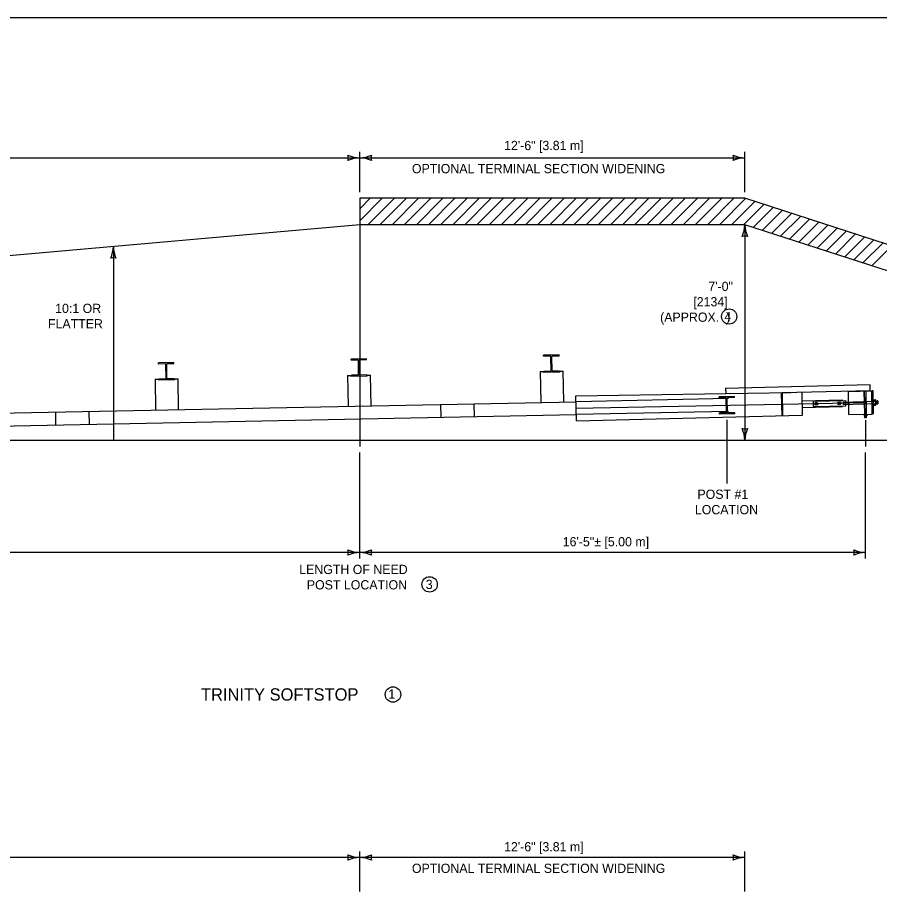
# Model space of a CAD drawing. Extents: x 49991.4 to 50021, y 49987.6 to 50011.4.
# Drawn here: x 50006.31 to 50011.91, y 49993.3 to 49999 of the extents above; entities that cross this region are included whole.
import ezdxf

# ---------------------------------------------------------------- set-up
doc = ezdxf.new("R2010")
doc.units = 0
for name, color, linetype in [('Level 1', 7, 'Continuous'), ('Level 2', 7, 'Continuous'), ('Level 3', 7, 'Continuous'), ('Level 5', 7, 'Continuous')]:
    doc.layers.add(name, color=color, linetype=linetype)

msp = doc.modelspace()

# ---------------------------------------------------------------- linework, layer by layer
at = {"layer": 'Level 1'}
for p, q in [((50011.0311, 49997.8254), (50008.5311, 49997.8254)), ((50008.5311, 49997.8254), (50008.5311, 49997.6537)), ((50008.6772, 49997.8254), (50008.5311, 49997.6793)), ((50008.5985, 49997.8254), (50008.5311, 49997.758)), ((50008.7559, 49997.8254), (50008.5841, 49997.6537)), ((50008.8346, 49997.8254), (50008.6628, 49997.6537)), ((50008.9133, 49997.8254), (50008.7415, 49997.6537)), ((50008.992, 49997.8254), (50008.8202, 49997.6537)), ((50009.0707, 49997.8254), (50008.8989, 49997.6537)), ((50009.1494, 49997.8254), (50008.9776, 49997.6537)), ((50009.2281, 49997.8254), (50009.0563, 49997.6537)), ((50009.3068, 49997.8254), (50009.135, 49997.6537)), ((50009.3855, 49997.8254), (50009.2137, 49997.6537)), ((50009.4642, 49997.8254), (50009.2924, 49997.6537)), ((50009.5429, 49997.8254), (50009.3711, 49997.6537)), ((50009.6216, 49997.8254), (50009.4498, 49997.6537)), ((50009.7003, 49997.8254), (50009.5286, 49997.6537)), ((50009.779, 49997.8254), (50009.6073, 49997.6537)), ((50009.8577, 49997.8254), (50009.686, 49997.6537)), ((50009.9364, 49997.8254), (50009.7647, 49997.6537)), ((50010.0151, 49997.8254), (50009.8434, 49997.6537)), ((50010.0938, 49997.8254), (50009.9221, 49997.6537)), ((50010.1725, 49997.8254), (50010.0008, 49997.6537)), ((50010.2512, 49997.8254), (50010.0795, 49997.6537)), ((50010.3299, 49997.8254), (50010.1582, 49997.6537)), ((50010.4086, 49997.8254), (50010.2369, 49997.6537)), ((50010.4873, 49997.8254), (50010.3156, 49997.6537)), ((50010.5661, 49997.8254), (50010.3943, 49997.6537)), ((50010.6448, 49997.8254), (50010.473, 49997.6537)), ((50010.7235, 49997.8254), (50010.5517, 49997.6537)), ((50010.8022, 49997.8254), (50010.6304, 49997.6537)), ((50010.8809, 49997.8254), (50010.7091, 49997.6537)), ((50010.9596, 49997.8254), (50010.7878, 49997.6537)), ((50015.8765, 49996.2537), (50011.0311, 49997.8254)), ((50011.0365, 49997.8236), (50010.8665, 49997.6537)), ((50011.0959, 49997.8044), (50010.9451, 49997.6537)), ((50011.1552, 49997.7851), (50011.0236, 49997.6537)), ((50011.2144, 49997.7659), (50011.0848, 49997.6362)), ((50011.2738, 49997.7467), (50011.1441, 49997.617)), ((50011.3331, 49997.7274), (50011.2035, 49997.5977)), ((50011.3924, 49997.7082), (50011.2628, 49997.5785)), ((50011.4518, 49997.6889), (50011.322, 49997.5593)), ((50011.5112, 49997.6697), (50011.3814, 49997.54)), ((50008.5311, 49997.6537), (50001.6559, 49997.0447)), ((50011.0311, 49997.6537), (50008.5311, 49997.6537)), ((50015.3468, 49996.2537), (50011.0311, 49997.6537)), ((50011.5704, 49997.6505), (50011.4407, 49997.5208)), ((50011.6297, 49997.6312), (50011.5, 49997.5015)), ((50011.6891, 49997.612), (50011.5594, 49997.4823)), ((50011.7484, 49997.5927), (50011.6187, 49997.463)), ((50011.8077, 49997.5735), (50011.678, 49997.4438)), ((50011.8671, 49997.5542), (50011.7373, 49997.4245)), ((50011.9264, 49997.535), (50011.7967, 49997.4053)), ((50011.9857, 49997.5158), (50011.856, 49997.386)), ((50009.8249, 49996.8081), (50009.7252, 49996.8061)), ((50009.7253, 49996.7993), (50009.7252, 49996.8061)), ((50009.7723, 49996.8002), (50009.7253, 49996.7993)), ((50009.7742, 49996.7019), (50009.7723, 49996.8002)), ((50009.825, 49996.8013), (50009.7781, 49996.8003)), ((50009.78, 49996.702), (50009.7781, 49996.8003)), ((50009.825, 49996.8013), (50009.8249, 49996.8081)), ((50007.3249, 49996.7581), (50007.2252, 49996.7561)), ((50007.2253, 49996.7493), (50007.2252, 49996.7561)), ((50007.2723, 49996.7502), (50007.2253, 49996.7493)), ((50007.2742, 49996.6519), (50007.2723, 49996.7502)), ((50007.325, 49996.7513), (50007.2781, 49996.7503)), ((50007.28, 49996.652), (50007.2781, 49996.7503)), ((50007.325, 49996.7513), (50007.3249, 49996.7581)), ((50008.5749, 49996.7831), (50008.4752, 49996.7811)), ((50008.4753, 49996.7743), (50008.4752, 49996.7811)), ((50008.5223, 49996.7752), (50008.4753, 49996.7743)), ((50008.5242, 49996.6769), (50008.5223, 49996.7752)), ((50008.575, 49996.7763), (50008.5281, 49996.7753)), ((50008.53, 49996.677), (50008.5281, 49996.7753)), ((50008.575, 49996.7763), (50008.5749, 49996.7831)), ((50009.7023, 49996.6999), (50009.7242, 49996.7003)), ((50009.7023, 49996.6999), (50009.7063, 49996.4999)), ((50009.7242, 49996.7003), (50009.7243, 49996.6942)), ((50009.8301, 49996.6963), (50009.7243, 49996.6942)), ((50009.7742, 49996.7019), (50009.7273, 49996.701)), ((50009.7274, 49996.6942), (50009.7273, 49996.701)), ((50009.827, 49996.703), (50009.78, 49996.702)), ((50009.8271, 49996.6962), (50009.827, 49996.703)), ((50009.83, 49996.7025), (50009.8518, 49996.7029)), ((50009.8301, 49996.6963), (50009.83, 49996.7025)), ((50009.8558, 49996.5029), (50009.8518, 49996.7029)), ((50007.2023, 49996.6499), (50007.2242, 49996.6503)), ((50007.2023, 49996.6499), (50007.2063, 49996.4499)), ((50007.2242, 49996.6503), (50007.2243, 49996.6442)), ((50007.3301, 49996.6463), (50007.2243, 49996.6442)), ((50007.2742, 49996.6519), (50007.2273, 49996.651)), ((50007.2274, 49996.6442), (50007.2273, 49996.651)), ((50007.327, 49996.653), (50007.28, 49996.652)), ((50007.3271, 49996.6462), (50007.327, 49996.653)), ((50007.33, 49996.6525), (50007.3518, 49996.6529)), ((50007.3301, 49996.6463), (50007.33, 49996.6525)), ((50007.3558, 49996.4529), (50007.3518, 49996.6529)), ((50008.4523, 49996.6749), (50008.4742, 49996.6753)), ((50008.4523, 49996.6749), (50008.4563, 49996.4749)), ((50008.4742, 49996.6753), (50008.4743, 49996.6692)), ((50008.5801, 49996.6713), (50008.4743, 49996.6692)), ((50008.5242, 49996.6769), (50008.4773, 49996.676)), ((50008.4774, 49996.6692), (50008.4773, 49996.676)), ((50008.577, 49996.678), (50008.53, 49996.677)), ((50008.5771, 49996.6712), (50008.577, 49996.678)), ((50008.58, 49996.6775), (50008.6018, 49996.6779)), ((50008.5801, 49996.6713), (50008.58, 49996.6775)), ((50008.6058, 49996.4779), (50008.6018, 49996.6779)), ((50011.8446, 49996.6141), (50010.9067, 49996.5906)), ((50010.9067, 49996.5921), (50010.9076, 49996.5562)), ((50011.8456, 49996.5741), (50011.2728, 49996.5622)), ((50011.7049, 49996.5705), (50011.8549, 49996.5743)), ((50011.8047, 49996.573), (50011.8071, 49996.4233)), ((50011.8067, 49996.5731), (50011.8091, 49996.4234)), ((50011.8165, 49996.5735), (50011.8189, 49996.4236)), ((50011.8209, 49996.4237), (50011.8185, 49996.5734)), ((50011.8456, 49996.5741), (50011.8446, 49996.6141)), ((50011.8641, 49996.5745), (50011.8549, 49996.5743)), ((50011.8573, 49996.4246), (50011.8549, 49996.5743)), ((50011.8665, 49996.4248), (50011.8641, 49996.5745)), ((50009.9344, 49996.542), (50011.3292, 49996.5642)), ((50009.9377, 49996.3809), (50009.9344, 49996.542)), ((50010.9244, 49996.5244), (50009.9352, 49996.5045)), ((50010.9636, 49996.5383), (50010.8639, 49996.5363)), ((50010.8641, 49996.5295), (50010.8639, 49996.5363)), ((50010.911, 49996.5304), (50010.8641, 49996.5295)), ((50010.913, 49996.4321), (50010.911, 49996.5304)), ((50010.9638, 49996.5315), (50010.9168, 49996.5306)), ((50010.9188, 49996.4322), (50010.9168, 49996.5306)), ((50010.9638, 49996.5315), (50010.9636, 49996.5383)), ((50011.2678, 49996.5621), (50011.2708, 49996.4113)), ((50011.2728, 49996.5622), (50011.2758, 49996.4114)), ((50011.4012, 49996.5642), (50011.4036, 49996.4145)), ((50011.4023, 49996.511), (50011.6641, 49996.5163)), ((50011.6642, 49996.5124), (50011.6641, 49996.5163)), ((50011.7073, 49996.4211), (50011.7049, 49996.5708)), ((50011.8672, 49996.5197), (50011.865, 49996.5196)), ((50011.8679, 49996.4798), (50011.8672, 49996.5197)), ((50011.8673, 49996.5172), (50011.8777, 49996.5174)), ((50001.6561, 49996.3389), (50009.9352, 49996.5045)), ((50009.0557, 49996.4869), (50009.0574, 49996.4032)), ((50009.2723, 49996.4913), (50009.274, 49996.4075)), ((50009.936, 49996.4615), (50011.8227, 49996.4992)), ((50011.4025, 49996.4676), (50011.665, 49996.4729)), ((50011.4741, 49996.5086), (50011.686, 49996.5128)), ((50011.4741, 49996.5086), (50011.4748, 49996.473)), ((50011.4748, 49996.473), (50011.6868, 49996.4772)), ((50011.6649, 49996.4768), (50011.665, 49996.4729)), ((50011.6692, 49996.5022), (50011.8653, 49996.5071)), ((50011.6692, 49996.5022), (50011.6695, 49996.4872)), ((50011.6695, 49996.4872), (50011.8654, 49996.4922)), ((50011.6863, 49996.4976), (50011.686, 49996.5128)), ((50011.6868, 49996.4772), (50011.6864, 49996.4927)), ((50011.8652, 49996.5096), (50011.8559, 49996.5094)), ((50011.8655, 49996.4897), (50011.8563, 49996.4895)), ((50011.8674, 49996.5103), (50011.8652, 49996.5102)), ((50011.8677, 49996.4891), (50011.8655, 49996.489)), ((50011.8679, 49996.4798), (50011.8657, 49996.4797)), ((50011.8674, 49996.5084), (50011.8778, 49996.5087)), ((50011.8677, 49996.491), (50011.8781, 49996.4912)), ((50011.8678, 49996.4822), (50011.8782, 49996.4825)), ((50011.8811, 49996.5128), (50011.8815, 49996.4873)), ((50011.8812, 49996.5096), (50011.8814, 49996.5101)), ((50011.8824, 49996.4913), (50011.8814, 49996.5101)), ((50011.8814, 49996.5101), (50011.8822, 49996.5088)), ((50011.8817, 49996.4901), (50011.8814, 49996.4954)), ((50011.8815, 49996.4904), (50011.8817, 49996.4901)), ((50011.8824, 49996.4913), (50011.8817, 49996.4901)), ((50011.8829, 49996.5101), (50011.8822, 49996.5088)), ((50011.8833, 49996.4901), (50011.8822, 49996.5088)), ((50011.8824, 49996.4913), (50011.8833, 49996.4901)), ((50011.884, 49996.4914), (50011.8829, 49996.5101)), ((50011.8829, 49996.5101), (50011.8837, 49996.5089)), ((50011.884, 49996.4914), (50011.8833, 49996.4901)), ((50011.8845, 49996.5101), (50011.8837, 49996.5089)), ((50011.8848, 49996.4902), (50011.8837, 49996.5089)), ((50011.884, 49996.4914), (50011.8848, 49996.4902)), ((50011.8856, 49996.4914), (50011.8845, 49996.5101)), ((50011.8845, 49996.5101), (50011.8853, 49996.5089)), ((50011.8856, 49996.4914), (50011.8848, 49996.4902)), ((50011.886, 49996.5102), (50011.8853, 49996.5089)), ((50011.8863, 49996.4902), (50011.8853, 49996.5089)), ((50011.8856, 49996.4914), (50011.8863, 49996.4902)), ((50011.8871, 49996.4914), (50011.886, 49996.5102)), ((50011.886, 49996.5102), (50011.8868, 49996.5089)), ((50011.8871, 49996.4914), (50011.8863, 49996.4902)), ((50011.8876, 49996.5102), (50011.8868, 49996.5089)), ((50011.8879, 49996.4902), (50011.8868, 49996.5089)), ((50011.8871, 49996.4914), (50011.8879, 49996.4902)), ((50011.8886, 49996.4915), (50011.8876, 49996.5102)), ((50011.8876, 49996.5102), (50011.8884, 49996.509)), ((50011.8886, 49996.4915), (50011.8879, 49996.4902)), ((50011.8891, 49996.5103), (50011.8884, 49996.509)), ((50011.8895, 49996.4903), (50011.8884, 49996.509)), ((50011.8886, 49996.4915), (50011.8895, 49996.4903)), ((50011.8902, 49996.4915), (50011.8891, 49996.5103)), ((50011.8891, 49996.5103), (50011.8899, 49996.509)), ((50011.8902, 49996.4915), (50011.8895, 49996.4903)), ((50011.8907, 49996.5103), (50011.8899, 49996.509)), ((50011.891, 49996.4903), (50011.8899, 49996.509)), ((50011.8902, 49996.4915), (50011.891, 49996.4903)), ((50011.8918, 49996.4915), (50011.8907, 49996.5103)), ((50011.8907, 49996.5103), (50011.8915, 49996.509)), ((50011.8918, 49996.4915), (50011.891, 49996.4903)), ((50011.8922, 49996.5103), (50011.8915, 49996.509)), ((50011.8925, 49996.4904), (50011.8915, 49996.509)), ((50011.8918, 49996.4915), (50011.8925, 49996.4904)), ((50011.8933, 49996.4916), (50011.8922, 49996.5103)), ((50011.8922, 49996.5103), (50011.893, 49996.5091)), ((50011.8933, 49996.4916), (50011.8925, 49996.4904)), ((50011.8938, 49996.5104), (50011.893, 49996.5091)), ((50011.8941, 49996.4904), (50011.893, 49996.5091)), ((50011.8933, 49996.4916), (50011.8941, 49996.4904)), ((50011.8948, 49996.4916), (50011.8938, 49996.5104)), ((50011.8938, 49996.5104), (50011.8946, 49996.5091)), ((50011.8948, 49996.4916), (50011.8941, 49996.4904)), ((50011.8946, 49996.5091), (50011.8948, 49996.4916)), ((50001.6561, 49996.2551), (50009.9369, 49996.4208)), ((50006.5557, 49996.4369), (50006.5574, 49996.3532)), ((50006.7723, 49996.4413), (50006.774, 49996.3575)), ((50010.926, 49996.4407), (50009.9369, 49996.4208)), ((50009.9377, 49996.3809), (50011.4035, 49996.4162)), ((50010.913, 49996.4321), (50010.866, 49996.4312)), ((50010.8662, 49996.4245), (50010.866, 49996.4312)), ((50010.9659, 49996.4264), (50010.8662, 49996.4245)), ((50010.9657, 49996.4332), (50010.9188, 49996.4322)), ((50010.9659, 49996.4264), (50010.9657, 49996.4332)), ((50011.7073, 49996.4208), (50011.8573, 49996.4246)), ((50011.8042, 49996.4232), (50011.8238, 49996.4237)), ((50011.8042, 49996.4215), (50011.8042, 49996.4232)), ((50011.8042, 49996.4215), (50011.8239, 49996.422)), ((50011.8054, 49996.4216), (50011.8056, 49996.4133)), ((50011.8207, 49996.4111), (50011.8077, 49996.4107)), ((50011.8088, 49996.4217), (50011.8088, 49996.4234)), ((50011.8093, 49996.4106), (50011.8109, 49996.4108)), ((50011.8095, 49996.4108), (50011.8093, 49996.4106)), ((50011.8099, 49996.41), (50011.8093, 49996.4106)), ((50011.8093, 49996.4094), (50011.8185, 49996.4102)), ((50011.8099, 49996.41), (50011.8093, 49996.4094)), ((50011.8099, 49996.4088), (50011.8093, 49996.4094)), ((50011.8093, 49996.4082), (50011.8185, 49996.409)), ((50011.8099, 49996.4088), (50011.8093, 49996.4082)), ((50011.8099, 49996.4076), (50011.8093, 49996.4082)), ((50011.8094, 49996.4069), (50011.8186, 49996.4078)), ((50011.8099, 49996.4076), (50011.8094, 49996.4069)), ((50011.81, 49996.4064), (50011.8094, 49996.4069)), ((50011.8094, 49996.4057), (50011.8186, 49996.4066)), ((50011.81, 49996.4064), (50011.8094, 49996.4057)), ((50011.81, 49996.4051), (50011.8094, 49996.4057)), ((50011.8094, 49996.4045), (50011.8186, 49996.4053)), ((50011.81, 49996.4051), (50011.8094, 49996.4045)), ((50011.81, 49996.4039), (50011.8094, 49996.4045)), ((50011.8094, 49996.4033), (50011.8186, 49996.4041)), ((50011.81, 49996.4039), (50011.8094, 49996.4033)), ((50011.81, 49996.4027), (50011.8094, 49996.4033)), ((50011.8094, 49996.402), (50011.8186, 49996.4029)), ((50011.81, 49996.4027), (50011.8094, 49996.402)), ((50011.81, 49996.4015), (50011.8094, 49996.402)), ((50011.8095, 49996.4008), (50011.8187, 49996.4017)), ((50011.8183, 49996.4236), (50011.8097, 49996.4234)), ((50011.8098, 49996.4217), (50011.8099, 49996.4134)), ((50011.8099, 49996.41), (50011.8191, 49996.4109)), ((50011.8099, 49996.4088), (50011.8192, 49996.4096)), ((50011.8099, 49996.4076), (50011.8192, 49996.4084)), ((50011.81, 49996.4064), (50011.8192, 49996.4072)), ((50011.81, 49996.4051), (50011.8192, 49996.406)), ((50011.81, 49996.4039), (50011.8192, 49996.4047)), ((50011.81, 49996.4027), (50011.8193, 49996.4035)), ((50011.81, 49996.4015), (50011.8193, 49996.4023)), ((50011.8183, 49996.4219), (50011.8185, 49996.4137)), ((50011.8191, 49996.4109), (50011.8185, 49996.4102)), ((50011.8192, 49996.4096), (50011.8185, 49996.4102)), ((50011.8192, 49996.4096), (50011.8185, 49996.409)), ((50011.8192, 49996.4084), (50011.8185, 49996.409)), ((50011.8192, 49996.4084), (50011.8186, 49996.4078)), ((50011.8192, 49996.4072), (50011.8186, 49996.4078)), ((50011.8192, 49996.4072), (50011.8186, 49996.4066)), ((50011.8192, 49996.406), (50011.8186, 49996.4066)), ((50011.8192, 49996.406), (50011.8186, 49996.4053)), ((50011.8192, 49996.4047), (50011.8186, 49996.4053)), ((50011.8192, 49996.4047), (50011.8186, 49996.4041)), ((50011.8193, 49996.4035), (50011.8186, 49996.4041)), ((50011.8193, 49996.4035), (50011.8186, 49996.4029)), ((50011.8193, 49996.4023), (50011.8186, 49996.4029)), ((50011.8193, 49996.4023), (50011.8187, 49996.4017)), ((50011.8193, 49996.4011), (50011.8187, 49996.4017)), ((50011.8191, 49996.4109), (50011.819, 49996.411)), ((50011.8193, 49996.4219), (50011.8192, 49996.4236)), ((50011.8226, 49996.422), (50011.8228, 49996.4138)), ((50011.8239, 49996.422), (50011.8238, 49996.4237)), ((50011.8665, 49996.4248), (50011.8573, 49996.4246)), ((50011.81, 49996.4015), (50011.8095, 49996.4008)), ((50011.8101, 49996.4002), (50011.8095, 49996.4008)), ((50011.8101, 49996.4002), (50011.8193, 49996.4011)), ((50011.8187, 49996.4004), (50011.8101, 49996.4002)), ((50011.8193, 49996.4011), (50011.8187, 49996.4004)), ((50000.2381, 49996.2551), (50015.8765, 49996.2537))]:
    msp.add_line(p, q, dxfattribs=at)
msp.add_lwpolyline([(49999.3835, 49998.9992), (50016.7501, 49998.9992), (50016.7501, 49987.7988), (49999.3835, 49987.7988)], close=True, dxfattribs=at)
for centre, radius in [((50011.4945, 49996.4912), 0.00975), ((50011.4945, 49996.4912), 0.00775), ((50011.6439, 49996.4942), 0.00975), ((50011.6439, 49996.4942), 0.00775)]:
    msp.add_circle(centre, radius, dxfattribs=at)
for centre, major_axis, start_param, end_param in [((50011.8777, 49996.5131), (0, 0.00431), 4.714734, 6.30331), ((50011.8777, 49996.513), (0, -0.00431), 0.020125, 1.600918), ((50011.8779, 49996.5044), (0, 0.00431), 4.793382, 6.30331), ((50011.878, 49996.4956), (0, -0.00431), 0.020125, 1.530052), ((50011.8781, 49996.4869), (0, 0.00431), 4.732514, 6.30331), ((50011.8781, 49996.4868), (0, -0.00431), 0.020125, 1.618692), ((50011.8077, 49996.4134), (0, -0.00267), 4.73531, 6.306106), ((50011.8077, 49996.4134), (0, 0.00272), 3.140677, 4.711474), ((50011.812, 49996.4135), (0, -0.00267), 4.733592, 6.253409), ((50011.8164, 49996.4136), (0, 0.00268), 3.197527, 4.725448), ((50011.8206, 49996.4138), (0, -0.0027), 4.748152, 6.318948), ((50011.8207, 49996.4137), (0, 0.00268), 3.153377, 4.724173)]:
    msp.add_ellipse(centre, major_axis=major_axis, ratio=0.790231, start_param=start_param, end_param=end_param, dxfattribs=at)
at = {"layer": 'Level 2'}
for centre, radius in [((50010.9297, 49997.0577), 0.0492), ((50008.985, 49995.3182), 0.05), ((50008.7474, 49994.6034), 0.05)]:
    msp.add_circle(centre, radius, dxfattribs=at)
at = {"layer": 'Level 3'}
for p, q in [((50008.5311, 49998.0882), (50008.5311, 49998.1282)), ((50011.0311, 49998.0882), (50011.0311, 49998.1282)), ((50001.6559, 49998.0882), (50008.5311, 49998.0882)), ((50008.5311, 49997.8654), (50008.5311, 49998.0882)), ((50008.5311, 49998.0882), (50011.0311, 49998.0882)), ((50011.0311, 49997.8654), (50011.0311, 49998.0882)), ((50011.0311, 49997.6537), (50011.0311, 49996.2542)), ((50006.9319, 49997.512), (50006.9319, 49996.2546)), ((50008.531, 49995.4854), (50008.531, 49996.1744)), ((50011.8144, 49995.4854), (50011.8144, 49996.174)), ((50008.531, 49995.5254), (50001.6561, 49995.5254)), ((50011.8144, 49995.5254), (50008.531, 49995.5254)), ((50008.5311, 49993.3247), (50008.5311, 49993.5845)), ((50011.0311, 49993.3247), (50011.0311, 49993.5845)), ((50008.5311, 49993.5445), (50001.6559, 49993.5445)), ((50011.0311, 49993.5445), (50008.5311, 49993.5445))]:
    msp.add_line(p, q, dxfattribs=at)
for centre, radius, start, end in [((50008.5402, 49998.3103), 0.2223, 247.456, 267.6395), ((50008.4028, 49998.0882), 0.0548, 342.1388, 17.8612), ((50008.5425, 49997.8555), 0.233, 92.8273, 112.0772), ((50008.5196, 49998.3209), 0.233, 272.8273, 292.0772), ((50008.5196, 49998.3209), 0.233, 272.8273, 292.0772), ((50008.5219, 49997.8661), 0.2223, 67.456, 87.6395), ((50008.5219, 49997.8661), 0.2223, 67.456, 87.6395), ((50008.6593, 49998.0882), 0.0548, 162.1388, 197.8612), ((50008.6593, 49998.0882), 0.0548, 162.1388, 197.8612), ((50011.0402, 49998.3103), 0.2223, 247.456, 267.6395), ((50010.9028, 49998.0882), 0.0548, 342.1388, 17.8612), ((50011.0402, 49998.3103), 0.2223, 247.456, 267.6395), ((50010.9028, 49998.0882), 0.0548, 342.1388, 17.8612), ((50011.0425, 49997.8555), 0.233, 92.8273, 112.0772), ((50011.0425, 49997.8555), 0.233, 92.8273, 112.0772), ((50010.8089, 49997.6628), 0.2223, 337.456, 357.6395), ((50011.2638, 49997.6651), 0.233, 182.8273, 202.0772), ((50011.0311, 49997.5254), 0.0548, 72.1388, 107.8612), ((50006.7097, 49997.5212), 0.2223, 337.456, 357.6395), ((50007.1646, 49997.5235), 0.233, 182.8273, 202.0772), ((50006.9319, 49997.3838), 0.0548, 72.1388, 107.8612), ((50011.0311, 49996.3824), 0.0548, 252.1388, 287.8612), ((50010.7983, 49996.2427), 0.233, 2.8273, 22.0772), ((50011.2532, 49996.245), 0.2223, 157.456, 177.6395), ((50008.5402, 49995.7476), 0.2223, 247.456, 267.6395), ((50008.4028, 49995.5254), 0.0548, 342.1388, 17.8612), ((50008.5402, 49995.7476), 0.2223, 247.456, 267.6395), ((50008.4028, 49995.5254), 0.0548, 342.1388, 17.8612), ((50008.5425, 49995.2927), 0.233, 92.8273, 112.0772), ((50008.5425, 49995.2927), 0.233, 92.8273, 112.0772), ((50008.5195, 49995.7581), 0.233, 272.8273, 292.0772), ((50008.5219, 49995.3033), 0.2223, 67.456, 87.6395), ((50008.6592, 49995.5254), 0.0548, 162.1388, 197.8612), ((50011.8235, 49995.7476), 0.2223, 247.456, 267.6395), ((50011.6862, 49995.5254), 0.0548, 342.1388, 17.8612), ((50011.8259, 49995.2927), 0.233, 92.8273, 112.0772), ((50008.5402, 49993.7666), 0.2223, 247.456, 267.6395), ((50008.4028, 49993.5445), 0.0548, 342.1388, 17.8612), ((50008.5402, 49993.7666), 0.2223, 247.456, 267.6395), ((50008.4028, 49993.5445), 0.0548, 342.1388, 17.8612), ((50008.5196, 49993.7772), 0.233, 272.8273, 292.0772), ((50008.6593, 49993.5445), 0.0548, 162.1388, 197.8612), ((50011.0402, 49993.7666), 0.2223, 247.456, 267.6395), ((50010.9028, 49993.5445), 0.0548, 342.1388, 17.8612), ((50008.5425, 49993.3118), 0.233, 92.8273, 112.0772), ((50008.5425, 49993.3118), 0.233, 92.8273, 112.0772), ((50008.5219, 49993.3223), 0.2223, 67.456, 87.6395), ((50011.0425, 49993.3118), 0.233, 92.8273, 112.0772)]:
    msp.add_arc(centre, radius, start, end, dxfattribs=at)
at = {"layer": 'Level 5'}
for p, q in [((50008.5311, 49997.6537), (50008.531, 49996.2143)), ((50010.9149, 49996.3877), (50010.9149, 49995.9735)), ((50011.8144, 49996.3836), (50011.8144, 49996.214))]:
    msp.add_line(p, q, dxfattribs=at)

# ---------------------------------------------------------------- texts
at = {"layer": 'Level 2'}
for s, height, p in [('12\'-6" [3.81 m]', 0.06, (50009.4683, 49998.1383)), ('OPTIONAL TERMINAL SECTION WIDENING', 0.06, (50008.87, 49997.9882)), ('7\'-0"', 0.06, (50010.7941, 49997.2235)), ('7\'-0"', 0.06, (50010.7941, 49997.2235)), ('[2134]', 0.06, (50010.6967, 49997.1235)), ('[2134]', 0.06, (50010.6967, 49997.1235)), ('10:1 OR', 0.06, (50006.5539, 49997.0806)), ('(APPROX.  )', 0.06, (50010.4812, 49997.0235)), ('(APPROX.  )', 0.06, (50010.4812, 49997.0235)), ('4', 0.06, (50010.899, 49997.0272)), ('FLATTER', 0.06, (50006.5075, 49996.9806)), ('POST #1', 0.06, (50010.7234, 49995.8735)), ('LOCATION', 0.06, (50010.707, 49995.7736)), ('16\'-5"± [5.00 m]', 0.06, (50009.849, 49995.5654)), ('LENGTH OF NEED', 0.06, (50008.1382, 49995.3854)), ('POST LOCATION', 0.06, (50008.1878, 49995.2855)), ('3', 0.06, (50008.9598, 49995.2882)), ('TRINITY SOFTSTOP', 0.08, (50007.5006, 49994.5634)), ('1', 0.06, (50008.7168, 49994.5765)), ('12\'-6" [3.81 m]', 0.06, (50009.4683, 49993.5845)), ('OPTIONAL TERMINAL SECTION WIDENING', 0.06, (50008.87, 49993.4445))]:
    msp.add_text(s, height=height, dxfattribs=at).set_placement(p)

doc.saveas('drawing.dxf')
